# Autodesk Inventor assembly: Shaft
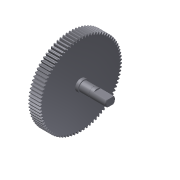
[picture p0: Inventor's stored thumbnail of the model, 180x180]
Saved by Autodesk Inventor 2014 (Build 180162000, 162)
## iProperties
Created: 2010-12
Part Number: Shaft
Document SubType Name: Assembly
Designer: Thom Tremblay
ClientObjectVersion: 1
Author: Thom Tremblay
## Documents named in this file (2)
- C:\Inventor 2014 Essentials\Assemblies\Chapter 08\c08-01\Design Accelerator\Shaft4.iam
- C:\Inventor 2014 Essentials\Assemblies\Chapter 08\c08-01\Design Accelerator\Shaft4.ipt
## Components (1 placed, 1 different names)
1. Shaft:1
